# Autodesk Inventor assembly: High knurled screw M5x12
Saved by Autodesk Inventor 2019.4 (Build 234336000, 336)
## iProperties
Created: 2021-08
Part Number: High knurled screw M5x12
Document SubType Name: Assembly
Designer: Administrator
Title: High knurled screw M5x12 v5
Author: Administrator
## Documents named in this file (2)
- c:\worker\convert-fusion-r06\tmp\job-1\20\output\files\f01db8e3-9ba6-469c-91a4-18b8ab1b818d\High knurled screw M5x12 v5_1.iam
- c:\worker\convert-fusion-r06\tmp\job-1\20\output\files\f01db8e3-9ba6-469c-91a4-18b8ab1b818d\_Knurled screw DIN 464-M5-12-ZB.ipt
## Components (1 placed, 1 different names)
1. _Knurled screw DIN 464-M5-12-ZB:1
